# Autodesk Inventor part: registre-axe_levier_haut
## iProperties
Author: chr
Shininess: 21.0
PropertySet Name: _Private Model Information
Length Units: 11269
Angle Units: 11286
Time Units: 11279
Mass Units: 11290
Length Display Precision: 3
Angle Display Precision: 2
Compacted: False
Created: 2001-06
Part Number: registre-axe_levier_haut
Material: Par défaut
Document SubType Name: Modélisation
Designer: chr
Control State: 0
Master: False
Checked Out: False
PropertySet Name: Design Tracking Control
Density: 0.0
Volumn: 0.0
Area: 0.0
PropertySet Name: Model Information
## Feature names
1. Extrusion1
2. Extrusion2
3. Hélicoïde1
